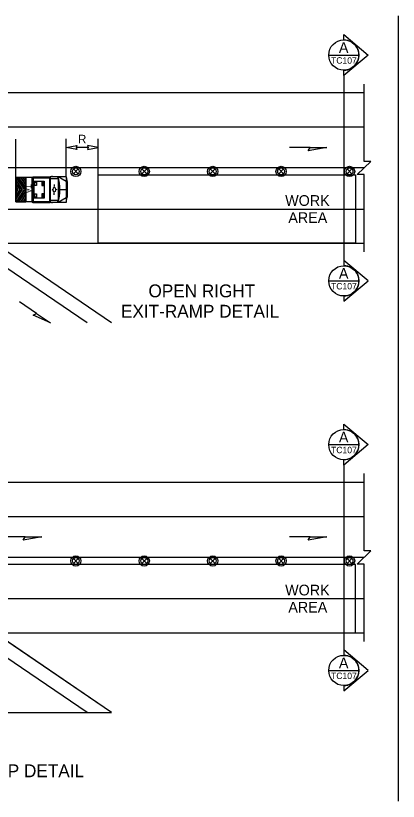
# Model space of a CAD drawing. Extents: x 99999 to 100116, y 99995 to 100013.
# Drawn here: x 100064.3 to 100067.88, y 100001.58 to 100008.92 of the extents above; entities that cross this region are included whole.
import ezdxf

# ---------------------------------------------------------------- set-up
doc = ezdxf.new("R2010")
doc.units = 0
for name, color, linetype in [('RD_MK_LineEdgeYellow', 7, 'Continuous'), ('RD_MK_LineLane', 7, 'Continuous'), ('SH_DE_DetailHeading2Text', 7, 'Continuous'), ('SH_TI_WZSectionCut', 7, 'Continuous'), ('TR_WZ_TrafficSafetyDrum', 7, 'Continuous'), ('TR_WZ_TransportableAttenuator', 7, 'Continuous'), ('TR_WZ_WorkAreaLabel', 7, 'Continuous'), ('TR_WZ_WorkZoneDetails', 7, 'Continuous'), ('TR_WZ_WorkZoneTextCurrent', 7, 'Continuous')]:
    doc.layers.add(name, color=color, linetype=linetype)

msp = doc.modelspace()

# ---------------------------------------------------------------- linework, layer by layer
at = {"layer": 'RD_MK_LineEdgeYellow'}
for p, q in [((100060.32, 100007.8789), (100067.555, 100007.8789)), ((100064.0968, 100007.1109), (100067.555, 100007.1109)), ((100064.9659, 100006.047), (100064.0249, 100006.6849)), ((100060.32, 100004.238), (100067.555, 100004.238)), ((100064.0968, 100003.47), (100067.555, 100003.47)), ((100064.9659, 100002.4061), (100064.0249, 100003.0439))]:
    msp.add_line(p, q, dxfattribs=at)
at = {"layer": 'RD_MK_LineLane'}
for points in [[(100067.555, 100007.4949), (100060.32, 100007.4949)], [(100067.555, 100003.854), (100060.32, 100003.854)]]:
    msp.add_lwpolyline(points, dxfattribs=at)
at = {"layer": 'SH_TI_WZSectionCut'}
for p, q in [((100067.3657, 100008.6913), (100067.3657, 100008.7412)), ((100067.3657, 100008.7412), (100067.5938, 100008.55)), ((100067.5938, 100008.55), (100067.3657, 100008.3589)), ((100067.3657, 100008.3589), (100067.3657, 100008.4088)), ((100067.3657, 100008.3589), (100067.3657, 100006.6309)), ((100067.3657, 100006.6309), (100067.3657, 100006.581)), ((100067.5939, 100006.4398), (100067.3657, 100006.6309)), ((100067.3657, 100006.2486), (100067.5939, 100006.4398)), ((100067.3657, 100006.2985), (100067.3657, 100006.2486)), ((100067.3657, 100005.0503), (100067.3657, 100005.1002)), ((100067.3657, 100005.1002), (100067.5938, 100004.9091)), ((100067.5938, 100004.9091), (100067.3657, 100004.718)), ((100067.3657, 100004.718), (100067.3657, 100004.7679)), ((100067.3657, 100004.718), (100067.3657, 100002.99)), ((100067.3657, 100002.99), (100067.3657, 100002.94)), ((100067.5939, 100002.7988), (100067.3657, 100002.99)), ((100067.3657, 100002.6077), (100067.5939, 100002.7988)), ((100067.3657, 100002.6576), (100067.3657, 100002.6077))]:
    msp.add_line(p, q, dxfattribs=at)
for points in [[(100067.2245, 100008.5501), (100067.5069, 100008.5501)], [(100067.2245, 100006.4398), (100067.5069, 100006.4398)], [(100067.2245, 100004.9091), (100067.5069, 100004.9091)], [(100067.2245, 100002.7988), (100067.5069, 100002.7988)]]:
    msp.add_lwpolyline(points, dxfattribs=at)
for centre in [(100067.3657, 100008.55), (100067.3657, 100006.4398), (100067.3657, 100004.9091), (100067.3657, 100002.7988)]:
    msp.add_circle(centre, 0.1412, dxfattribs=at)
for centre in [(100067.3657, 100008.55), (100067.3657, 100006.4398), (100067.3657, 100004.9091), (100067.3657, 100002.7988)]:
    msp.add_arc(centre, 0.1412, 269.99779, 90.00221, dxfattribs=at)
at = {"layer": 'TR_WZ_TrafficSafetyDrum'}
for p, q in [((100064.8363, 100007.4855), (100064.8815, 100007.4403)), ((100064.8815, 100007.4855), (100064.8363, 100007.4403)), ((100065.4763, 100007.4855), (100065.5215, 100007.4403)), ((100065.5215, 100007.4855), (100065.4763, 100007.4403)), ((100066.1163, 100007.4855), (100066.1615, 100007.4403)), ((100066.1615, 100007.4855), (100066.1163, 100007.4403)), ((100066.7563, 100007.4855), (100066.8015, 100007.4403)), ((100066.8015, 100007.4855), (100066.7563, 100007.4403)), ((100067.3963, 100007.4855), (100067.4415, 100007.4403)), ((100067.4415, 100007.4855), (100067.3963, 100007.4403)), ((100064.8363, 100003.8446), (100064.8815, 100003.7993)), ((100064.8815, 100003.8446), (100064.8363, 100003.7993)), ((100065.4763, 100003.8446), (100065.5215, 100003.7993)), ((100065.5215, 100003.8446), (100065.4763, 100003.7993)), ((100066.1163, 100003.8446), (100066.1615, 100003.7993)), ((100066.1615, 100003.8446), (100066.1163, 100003.7993)), ((100066.7563, 100003.8446), (100066.8015, 100003.7993)), ((100066.8015, 100003.8446), (100066.7563, 100003.7993)), ((100067.3963, 100003.8446), (100067.4415, 100003.7993)), ((100067.4415, 100003.8446), (100067.3963, 100003.7993))]:
    msp.add_line(p, q, dxfattribs=at)
for centre, radius in [((100064.8589, 100007.4629), 0.048), ((100064.8589, 100007.4629), 0.048), ((100065.4989, 100007.4629), 0.048), ((100065.4989, 100007.4629), 0.048), ((100066.1389, 100007.4629), 0.048), ((100066.1389, 100007.4629), 0.048), ((100066.7789, 100007.4629), 0.048), ((100066.7789, 100007.4629), 0.048), ((100067.4189, 100007.4629), 0.048), ((100067.4189, 100007.4629), 0.048), ((100064.8589, 100007.4629), 0.032), ((100065.4989, 100007.4629), 0.032), ((100066.1389, 100007.4629), 0.032), ((100066.7789, 100007.4629), 0.032), ((100067.4189, 100007.4629), 0.032), ((100064.8589, 100003.822), 0.048), ((100064.8589, 100003.822), 0.048), ((100064.8589, 100003.822), 0.032), ((100065.4989, 100003.822), 0.048), ((100065.4989, 100003.822), 0.048), ((100065.4989, 100003.822), 0.032), ((100066.1389, 100003.822), 0.048), ((100066.1389, 100003.822), 0.048), ((100066.1389, 100003.822), 0.032), ((100066.7789, 100003.822), 0.048), ((100066.7789, 100003.822), 0.048), ((100066.7789, 100003.822), 0.032), ((100067.4189, 100003.822), 0.048), ((100067.4189, 100003.822), 0.048), ((100067.4189, 100003.822), 0.032)]:
    msp.add_circle(centre, radius, dxfattribs=at)
at = {"layer": 'TR_WZ_TransportableAttenuator'}
for p, q in [((100064.2964, 100007.3836), (100064.3565, 100007.293)), ((100064.2964, 100007.3544), (100064.2964, 100007.3836)), ((100064.3565, 100007.293), (100064.2964, 100007.3836)), ((100064.2964, 100007.3836), (100064.2964, 100007.3544)), ((100064.3775, 100007.2924), (100064.3026, 100007.405)), ((100064.3026, 100007.405), (100064.323, 100007.405)), ((100064.3026, 100007.405), (100064.3775, 100007.2924)), ((100064.323, 100007.405), (100064.3026, 100007.405)), ((100064.323, 100007.405), (100064.3907, 100007.3023)), ((100064.3907, 100007.3023), (100064.323, 100007.405)), ((100064.3907, 100007.3355), (100064.3451, 100007.405)), ((100064.3451, 100007.405), (100064.3655, 100007.405)), ((100064.3655, 100007.405), (100064.3451, 100007.405)), ((100064.3451, 100007.405), (100064.3907, 100007.3355)), ((100064.3655, 100007.405), (100064.3907, 100007.3669)), ((100064.3907, 100007.3669), (100064.3655, 100007.405)), ((100064.3907, 100007.1797), (100064.3907, 100007.405)), ((100064.4551, 100007.405), (100064.3907, 100007.405)), ((100064.3907, 100007.3669), (100064.3907, 100007.3355)), ((100064.3907, 100007.3355), (100064.3907, 100007.3669)), ((100064.4475, 100007.4009), (100064.4475, 100007.1834)), ((100064.4511, 100007.4082), (100064.4546, 100007.4082)), ((100064.4546, 100007.4082), (100064.4546, 100007.1761)), ((100064.4551, 100007.4121), (100064.6177, 100007.4121)), ((100064.4551, 100007.4121), (100064.4551, 100007.1721)), ((100064.4551, 100007.4046), (100064.4551, 100007.1797)), ((100064.4598, 100007.4026), (100064.4598, 100007.1817)), ((100064.4598, 100007.4026), (100064.6131, 100007.4026)), ((100064.6131, 100007.4026), (100064.6131, 100007.1817)), ((100064.6177, 100007.4121), (100064.6177, 100007.1721)), ((100064.6199, 100007.4121), (100064.6199, 100007.1721)), ((100064.7691, 100007.4121), (100064.6199, 100007.4121)), ((100064.6931, 100007.3935), (100064.6199, 100007.3935)), ((100064.6402, 100007.4155), (100064.6312, 100007.4155)), ((100064.6931, 100007.4121), (100064.6836, 100007.3935)), ((100064.6931, 100007.4121), (100064.6931, 100007.1721)), ((100064.6944, 100007.4121), (100064.6944, 100007.1721)), ((100064.7691, 100007.3682), (100064.6944, 100007.4121)), ((100064.7691, 100007.4121), (100064.7691, 100007.1721)), ((100064.7691, 100007.4121), (100064.7764, 100007.3637)), ((100064.7764, 100007.3637), (100064.7764, 100007.2206)), ((100064.3372, 100007.2933), (100064.2964, 100007.3544)), ((100064.2964, 100007.3544), (100064.3372, 100007.2933)), ((100064.2964, 100007.3235), (100064.3173, 100007.2925)), ((100064.2964, 100007.2611), (100064.2964, 100007.3235)), ((100064.3173, 100007.2925), (100064.2964, 100007.3235)), ((100064.2964, 100007.3235), (100064.2964, 100007.2611)), ((100064.2964, 100007.2319), (100064.3372, 100007.2933)), ((100064.3372, 100007.2933), (100064.2964, 100007.2319)), ((100064.3565, 100007.293), (100064.2964, 100007.2025)), ((100064.2964, 100007.2025), (100064.3565, 100007.293)), ((100064.3173, 100007.2925), (100064.2964, 100007.2611)), ((100064.2964, 100007.2611), (100064.3173, 100007.2925)), ((100064.3025, 100007.1796), (100064.3775, 100007.2924)), ((100064.3775, 100007.2924), (100064.3025, 100007.1796)), ((100064.3907, 100007.3023), (100064.3907, 100007.2822)), ((100064.3907, 100007.2822), (100064.3907, 100007.3023)), ((100064.4475, 100007.309), (100064.4546, 100007.3045)), ((100064.4494, 100007.2921), (100064.4527, 100007.2921)), ((100064.4511, 100007.2955), (100064.4511, 100007.2888)), ((100064.6335, 100007.2923), (100064.6434, 100007.2922)), ((100064.6462, 100007.2917), (100064.6462, 100007.2917)), ((100064.6573, 100007.3397), (100064.6573, 100007.3203)), ((100064.6811, 100007.2923), (100064.6711, 100007.2922)), ((100064.7691, 100007.2921), (100064.7091, 100007.2921)), ((100064.2964, 100007.2025), (100064.2964, 100007.2319)), ((100064.2964, 100007.2319), (100064.2964, 100007.2025)), ((100064.3907, 100007.2822), (100064.3226, 100007.1796)), ((100064.3226, 100007.1796), (100064.3907, 100007.2822)), ((100064.3446, 100007.1796), (100064.3907, 100007.2491)), ((100064.3907, 100007.2491), (100064.3446, 100007.1796)), ((100064.3907, 100007.2159), (100064.3662, 100007.1796)), ((100064.3662, 100007.1796), (100064.3907, 100007.2159)), ((100064.3907, 100007.2491), (100064.3907, 100007.2159)), ((100064.3907, 100007.2159), (100064.3907, 100007.2491)), ((100064.4475, 100007.2752), (100064.4546, 100007.2797)), ((100064.6573, 100007.2446), (100064.6573, 100007.264)), ((100064.7691, 100007.2161), (100064.6944, 100007.1721)), ((100064.7691, 100007.1721), (100064.7764, 100007.2206)), ((100064.3226, 100007.1796), (100064.3025, 100007.1796)), ((100064.3025, 100007.1796), (100064.3226, 100007.1796)), ((100064.3662, 100007.1796), (100064.3446, 100007.1796)), ((100064.3446, 100007.1796), (100064.3662, 100007.1796)), ((100064.4551, 100007.1797), (100064.3907, 100007.1797)), ((100064.4511, 100007.1761), (100064.4546, 100007.1761)), ((100064.4551, 100007.1721), (100064.6177, 100007.1721)), ((100064.4598, 100007.1817), (100064.6131, 100007.1817)), ((100064.6931, 100007.1907), (100064.6199, 100007.1907)), ((100064.7691, 100007.1721), (100064.6199, 100007.1721)), ((100064.6402, 100007.1688), (100064.6312, 100007.1688)), ((100064.6852, 100007.1907), (100064.6931, 100007.1721))]:
    msp.add_line(p, q, dxfattribs=at)
for points in [[(100064.3907, 100007.1796), (100064.2964, 100007.1796), (100064.2964, 100007.405), (100064.3907, 100007.405)], [(100064.4678, 100007.3721), (100064.5638, 100007.3721), (100064.5638, 100007.2121), (100064.4678, 100007.2121)], [(100064.4758, 100007.3621), (100064.4918, 100007.3621), (100064.4918, 100007.3321), (100064.4758, 100007.3321)], [(100064.5558, 100007.3621), (100064.5398, 100007.3621), (100064.5398, 100007.3321), (100064.5558, 100007.3321)], [(100064.4758, 100007.2521), (100064.4918, 100007.2521), (100064.4918, 100007.2221), (100064.4758, 100007.2221)], [(100064.5558, 100007.2521), (100064.5398, 100007.2521), (100064.5398, 100007.2221), (100064.5558, 100007.2221)]]:
    msp.add_lwpolyline(points, close=True, dxfattribs=at)
msp.add_lwpolyline([(100064.3907, 100007.405), (100064.2964, 100007.405), (100064.2964, 100007.1796), (100064.3907, 100007.1797)], dxfattribs=at)
for centre, major_axis, start_param, end_param in [((100064.4511, 100007.4009), (0, 0.00732), 6.283185, 7.853982), ((100064.5878, 100007.2921), (0, 0.2519), 4.215852, 5.209111), ((100064.4511, 100007.1834), (0, -0.00732), 4.712389, 6.283185)]:
    msp.add_ellipse(centre, major_axis=major_axis, ratio=0.481608, start_param=start_param, end_param=end_param, dxfattribs=at)
for centre, major_axis in [((100064.4511, 100007.2921), (0, -0.00338)), ((100064.6573, 100007.2921), (0, -0.0231))]:
    msp.add_ellipse(centre, major_axis=major_axis, ratio=0.481608, dxfattribs=at)
at = {"layer": 'TR_WZ_WorkZoneDetails'}
for p, q in [((100067.875, 100008.9181), (100067.875, 100001.5759)), ((100060.32, 100008.1989), (100067.555, 100008.1989)), ((100064.2964, 100007.405), (100064.2964, 100007.7642)), ((100064.7691, 100007.4121), (100064.7691, 100007.7683)), ((100065.0668, 100007.4309), (100065.0668, 100007.7683)), ((100064.973, 100007.6869), (100064.8628, 100007.6869)), ((100067.0492, 100007.6869), (100066.8563, 100007.6869)), ((100065.1937, 100006.047), (100064.0968, 100006.7909)), ((100064.0968, 100006.7909), (100067.555, 100006.7909)), ((100064.492, 100006.1352), (100064.3323, 100006.2435)), ((100060.32, 100004.558), (100067.555, 100004.558)), ((100064.3844, 100004.046), (100064.1915, 100004.046)), ((100067.0492, 100004.046), (100066.8563, 100004.046)), ((100065.1937, 100002.4061), (100064.0968, 100003.15)), ((100064.0968, 100003.15), (100067.555, 100003.15))]:
    msp.add_line(p, q, dxfattribs=at)
for points in [[(100067.555, 100006.7109), (100067.555, 100007.433), (100067.491, 100007.433), (100067.619, 100007.5569), (100067.555, 100007.5569), (100067.555, 100008.2789)], [(100067.555, 100003.07), (100067.555, 100003.792), (100067.491, 100003.792), (100067.619, 100003.9159), (100067.555, 100003.9159), (100067.555, 100004.638)]]:
    msp.add_lwpolyline(points, dxfattribs=at)
for points in [[(100064.7691, 100007.6869), (100064.8674, 100007.7062), (100064.8628, 100007.6869), (100064.8674, 100007.6676)], [(100065.0668, 100007.6869), (100064.9685, 100007.7062), (100064.973, 100007.6869), (100064.9685, 100007.6676)], [(100067.2065, 100007.6869), (100067.0314, 100007.6561), (100067.0492, 100007.6869)], [(100065.0668, 100006.7909), (100065.0668, 100007.4309), (100067.475, 100007.4309), (100067.475, 100006.7909)], [(100064.6221, 100006.047), (100064.4599, 100006.1197), (100064.492, 100006.1352)], [(100064.5416, 100004.046), (100064.3665, 100004.0151), (100064.3844, 100004.046)], [(100067.2065, 100004.046), (100067.0314, 100004.0151), (100067.0492, 100004.046)], [(100060.4, 100003.15), (100062.6438, 100003.15), (100063.746, 100002.4061), (100065.1937, 100002.4061), (100064.0968, 100003.15), (100065.8504, 100003.15), (100067.475, 100003.15), (100067.475, 100003.79), (100060.4, 100003.79)]]:
    msp.add_lwpolyline(points, close=True, dxfattribs=at)

# ---------------------------------------------------------------- texts
at = {"layer": 'SH_DE_DetailHeading2Text'}
for s, p in [('OPEN RIGHT', (100065.5382, 100006.2863)), ('EXIT-RAMP DETAIL', (100065.2814, 100006.0963)), ('CLOSED RIGHT EXIT-RAMP DETAIL', (100062.2073, 100001.8009))]:
    msp.add_text(s, height=0.12, rotation=360, dxfattribs=at).set_placement(p)
at = {"layer": 'SH_TI_WZSectionCut'}
for s, height, rotation, p in [('A', 0.1, 0.00995, (100067.3195, 100008.5707)), ('TC107', 0.06, 360, (100067.2459, 100008.4701)), ('A', 0.1, 0.00995, (100067.3195, 100006.4604)), ('TC107', 0.06, 360, (100067.2459, 100006.3598)), ('A', 0.1, 0.00995, (100067.3195, 100004.9297)), ('TC107', 0.06, 360, (100067.2459, 100004.8291)), ('A', 0.1, 0.00995, (100067.3195, 100002.8195)), ('TC107', 0.06, 360, (100067.2459, 100002.7188))]:
    msp.add_text(s, height=height, rotation=rotation, dxfattribs=at).set_placement(p)
at = {"layer": 'TR_WZ_TransportableAttenuator'}
msp.add_text('TA', height=0.048, rotation=270, dxfattribs=at).set_placement((100064.3951, 100007.3448))
at = {"layer": 'TR_WZ_WorkAreaLabel'}
for s, p in [('WORK', (100066.8169, 100007.1409)), ('AREA', (100066.8465, 100006.9809)), ('WORK', (100066.8169, 100003.5)), ('AREA', (100066.8465, 100003.34))]:
    msp.add_text(s, height=0.1, dxfattribs=at).set_placement(p)
at = {"layer": 'TR_WZ_WorkZoneTextCurrent'}
msp.add_text('R', height=0.08, dxfattribs=at).set_placement((100064.8804, 100007.7249))

doc.saveas('drawing.dxf')
